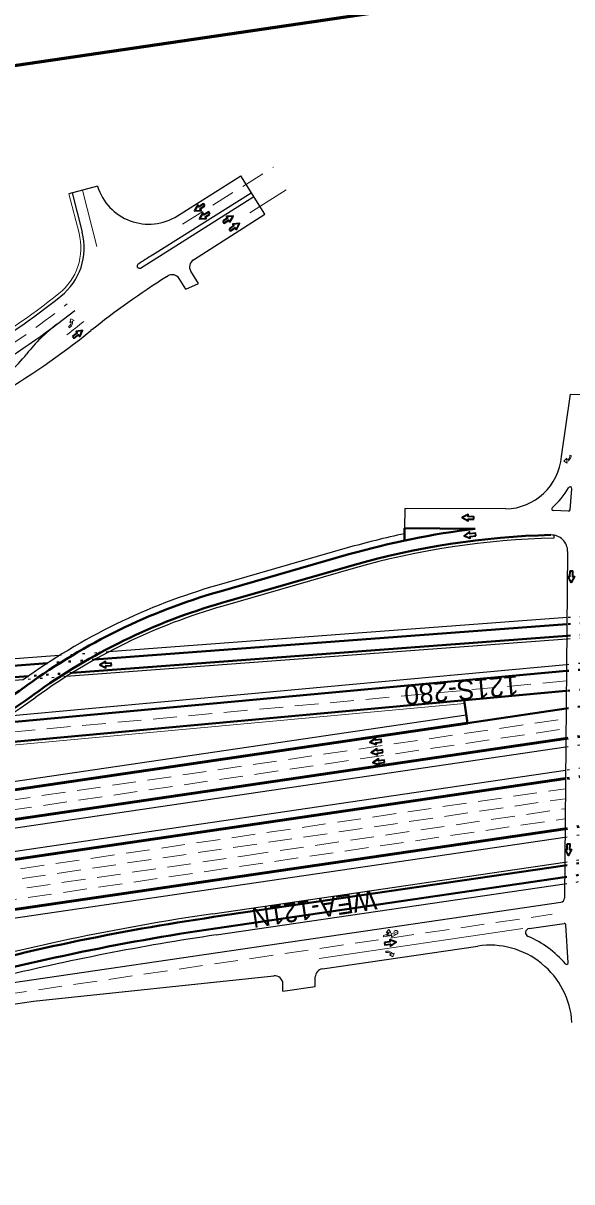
# Model space of a CAD drawing. Extents: x 2329387 to 2347382, y 6951580 to 6987999.
# Drawn here: x 2334179 to 2334845, y 6964414 to 6965820 of the extents above; entities that cross this region are included whole.
import ezdxf

# ---------------------------------------------------------------- set-up
doc = ezdxf.new("R2010")
doc.units = 0
doc.header["$LTSCALE"] = 9.6
doc.header["$PDMODE"] = 32
doc.header["$PDSIZE"] = 4.8
doc.linetypes.add('DOTTED', pattern=[1.5, 0.3, -1.2])
doc.linetypes.add('MEDIUM_DASHED', pattern=[4.5, 3, -1.5])
for name, color, linetype, lineweight in [('26', 7, 'Continuous', 53), ('27', 7, 'Continuous', 40), ('28', 7, 'Continuous', 25), ('30', 7, 'Continuous', 13), ('41', 7, 'Continuous', 35), ('50', 7, 'MEDIUM_DASHED', 13), ('60', 7, 'Continuous', 25), ('62', 7, 'Continuous', 60)]:
    doc.layers.add(name, color=color, linetype=linetype, lineweight=lineweight)
doc.layers.add('40', color=7, linetype='Continuous')

msp = doc.modelspace()

# ---------------------------------------------------------------- linework, layer by layer
at = {"layer": '26', "lineweight": 25}
for p, q in [((2333856.94, 6964854.018), (2334717.176, 6964980.367)), ((2333865.078, 6964798.612), (2334838.157, 6964941.536)), ((2333460.788, 6964710.931), (2334837.888, 6964913.196)), ((2333954.558, 6964702.596), (2334837.12, 6964832.225))]:
    msp.add_line(p, q, dxfattribs=at)
at = {"layer": '26'}
for p, q in [((2333858.393, 6964844.124), (2334718.629, 6964970.474)), ((2333863.625, 6964808.506), (2334838.253, 6964951.657)), ((2333462.241, 6964701.037), (2334837.792, 6964903.075)), ((2334058.85, 6964728.022), (2334837.216, 6964842.346))]:
    msp.add_line(p, q, dxfattribs=at)
at = {"layer": '26', "linetype": 'DOTTED', "lineweight": 25}
for p, q in [((2334838.157, 6964941.536), (2334914.266, 6964952.715)), ((2334913.997, 6964924.375), (2334837.888, 6964913.196)), ((2334837.12, 6964832.225), (2334913.23, 6964843.404))]:
    msp.add_line(p, q, dxfattribs=at)
at = {"layer": '26', "linetype": 'DOTTED'}
for p, q in [((2334838.253, 6964951.657), (2334914.362, 6964962.836)), ((2334913.901, 6964914.254), (2334837.792, 6964903.075)), ((2334837.216, 6964842.346), (2334913.326, 6964853.525))]:
    msp.add_line(p, q, dxfattribs=at)
at = {"layer": '27'}
for p, q in [((2334642.281, 6965192.145), (2334642.431, 6965207.145)), ((2334642.431, 6965207.145), (2334728.038, 6965206.29)), ((2334574.816, 6965175.343), (2334416.81, 6965129.922)), ((2334578.683, 6965161.887), (2334420.678, 6965116.467)), ((2334839.569, 6965090.471), (2334265.921, 6965047.543)), ((2334839.436, 6965076.422), (2334238.653, 6965031.463)), ((2334208.79, 6965043.268), (2333525.879, 6964992.163)), ((2334185.648, 6965027.497), (2333498.596, 6964976.082)), ((2334146.832, 6964969.959), (2334839.031, 6965033.749)), ((2334838.802, 6965009.626), (2334095.849, 6964941.159)), ((2334714.561, 6964998.176), (2334718.629, 6964970.474)), ((2334718.629, 6964970.474), (2334838.598, 6964988.094)), ((2334410.301, 6964735.17), (2334836.794, 6964797.812)), ((2334412.335, 6964721.319), (2334836.659, 6964783.642))]:
    msp.add_line(p, q, dxfattribs=at)
at = {"layer": '27', "lineweight": 25}
for p, q in [((2334823.447, 6965198.918), (2334823.529, 6965194.919)), ((2334572.605, 6965183.031), (2334414.6, 6965137.611)), ((2334579.788, 6965158.043), (2334421.783, 6965112.623)), ((2334839.645, 6965098.499), (2334283.038, 6965056.846)), ((2334839.398, 6965072.408), (2334231.393, 6965026.909)), ((2334223.01, 6965052.354), (2333541.47, 6965001.352)), ((2334161.708, 6964979.364), (2334839.107, 6965041.79)), ((2334179.397, 6965023.018), (2333490.801, 6964971.488)), ((2334409.719, 6964739.127), (2334836.832, 6964801.861)), ((2334413.498, 6964713.403), (2334836.583, 6964775.545))]:
    msp.add_line(p, q, dxfattribs=at)
at = {"layer": '27', "linetype": 'DOTTED'}
for p, q in [((2334915.626, 6965096.163), (2334839.569, 6965090.471)), ((2334915.493, 6965082.113), (2334839.436, 6965076.422)), ((2334265.921, 6965047.543), (2334214.256, 6965043.677)), ((2334839.031, 6965033.749), (2334915.101, 6965040.759)), ((2334238.653, 6965031.463), (2334185.648, 6965027.497)), ((2334914.872, 6965016.636), (2334838.802, 6965009.626)), ((2334838.598, 6964988.094), (2334914.708, 6964999.273)), ((2334836.794, 6964797.812), (2334912.903, 6964808.991)), ((2334836.659, 6964783.642), (2334912.769, 6964794.821))]:
    msp.add_line(p, q, dxfattribs=at)
at = {"layer": '27', "linetype": 'DOTTED', "lineweight": 25}
for p, q in [((2334915.575, 6965104.181), (2334839.645, 6965098.499)), ((2334915.455, 6965078.099), (2334839.398, 6965072.408)), ((2334283.038, 6965056.846), (2334225.125, 6965052.513)), ((2334839.107, 6965041.79), (2334915.177, 6965048.8)), ((2334231.393, 6965026.909), (2334179.397, 6965023.018)), ((2334836.832, 6964801.861), (2334912.942, 6964813.04)), ((2334836.583, 6964775.545), (2334912.692, 6964786.724))]:
    msp.add_line(p, q, dxfattribs=at)
at = {"layer": '27', "lineweight": 13}
msp.add_line((2334715.143, 6964994.213), (2334086.159, 6964936.249), dxfattribs=at)
at = {"layer": '27'}
for centre, radius, start, end in [((2339406.145, 6959556.474), 7976, 170.51466, 170.51466), ((2334842.948, 6964242.579), 970.538, 96.79971, 106.03781), ((2334842.948, 6964242.579), 956.538, 91.37922, 106.03791), ((2334624.015, 6964409.113), 750, 106.03791, 125.92709), ((2334624.015, 6964409.113), 736, 106.03791, 125.92709), ((2333743.882, 6965623.759), 750, 278.35573, 305.92709), ((2333743.882, 6965623.759), 764, 278.35573, 305.92709), ((2334828.642, 6961886.94), 2878.789, 98.35573, 105.37884), ((2334828.642, 6961886.94), 2864.789, 98.35573, 105.37884)]:
    msp.add_arc(centre, radius, start, end, dxfattribs=at)
at = {"layer": '27', "lineweight": 25}
for centre, radius, start, end in [((2334842.948, 6964242.579), 978.538, 101.82861, 106.03781), ((2334842.948, 6964242.579), 952.538, 91.16817, 106.03791), ((2334624.015, 6964409.113), 758, 106.03791, 125.92709), ((2334624.015, 6964409.113), 732, 106.03791, 125.92709), ((2333743.882, 6965623.759), 768, 278.35573, 305.92709), ((2334828.642, 6961886.94), 2882.789, 98.35573, 105.37884), ((2334828.642, 6961886.94), 2856.789, 98.35573, 103.83151)]:
    msp.add_arc(centre, radius, start, end, dxfattribs=at)
at = {"layer": '28'}
for p, q in [((2334366.494, 6965586.06), (2334443.436, 6965634.56)), ((2334472.751, 6965588.054), (2334443.436, 6965634.56)), ((2334269.683, 6965622.011), (2334234.765, 6965612.992)), ((2334238.638, 6965613.992), (2334250.993, 6965566.156)), ((2334336.431, 6965538.74), (2334456.234, 6965614.257)), ((2334321.554, 6965522.86), (2334459.166, 6965609.604)), ((2334385.955, 6965532.721), (2334472.751, 6965588.054)), ((2334353.229, 6965512.092), (2334354.944, 6965513.173)), ((2334832.876, 6965294.023), (2334844.015, 6965369.845)), ((2334844.028, 6965369.845), (2334913.874, 6965369.183)), ((2334843.4, 6965229.553), (2334845.307, 6965255.024)), ((2334841.329, 6965227.704), (2334822.856, 6965228.408)), ((2334840.405, 6965178.656), (2334836.417, 6964758.062)), ((2334146.907, 6964652.517), (2334832.144, 6964753.163)), ((2334793.517, 6964721.21), (2334836.014, 6964727.452)), ((2334841.153, 6964679.739), (2334838.301, 6964725.598)), ((2334542.559, 6964672.221), (2334731.324, 6964699.947)), ((2334191.855, 6964632.839), (2334483.531, 6964663.831)), ((2334533.946, 6964650.742), (2334534.012, 6964662.384)), ((2334494.538, 6964644.954), (2334494.588, 6964653.831)), ((2334494.538, 6964644.954), (2334533.946, 6964650.742)), ((2333814.811, 6964577.46), (2334191.855, 6964632.839))]:
    msp.add_line(p, q, dxfattribs=at)
at = {"layer": '28', "lineweight": 13}
msp.add_line((2334538.709, 6964684.795), (2334786.13, 6964721.136), dxfattribs=at)
at = {"layer": '28'}
msp.add_lwpolyline([(2334765.219, 6965230.4), (2334642.681, 6965230.938), (2334642.431, 6965207.145)], dxfattribs=at)
for centre, radius, start, end in [((2334331.833, 6965641.047), 65, 197.02964, 302.22536), ((2334178.376, 6965547.4), 75, 308.53995, 14.48202), ((2334886.479, 6964666.135), 1031.5, 122.22536, 123.3977), ((2334886.479, 6964666.135), 1000, 122.22536, 128.67685), ((2333636.625, 6966227.501), 944.5, 300.51546, 308.53995), ((2333636.625, 6966227.501), 968.5, 300.51546, 308.67685), ((2333636.625, 6966227.501), 1000, 300.51546, 308.67685), ((2334340.839, 6965295.044), 200, 127.06101, 141.87247), ((2334053.12, 6965520.868), 165.757, 300.51546, 321.87247), ((2334763.208, 6965300.324), 69.953, 271.64718, 354.83201), ((2334763.208, 6965300.324), 89.953, 310.50417, 330.59272), ((2334843.313, 6965255.174), 2, 355.71736, 150.59272), ((2334822.932, 6965230.407), 2, 130.50417, 267.81725), ((2334841.405, 6965229.703), 2, 267.81724, 355.71735), ((2334820.406, 6965178.845), 20, 359.45667, 91.37922), ((2334831.417, 6964758.109), 5, 278.35573, 359.45667), ((2334836.305, 6964725.473), 2, 3.55868, 98.35573), ((2334794.243, 6964716.263), 5, 98.35573, 247.22612), ((2334745.856, 6964601.008), 100, 3.55868, 98.35573), ((2334745.856, 6964601.008), 120, 40.11433, 67.22612), ((2334544.012, 6964662.327), 10, 98.35573, 179.67402), ((2334839.157, 6964679.615), 2, 220.11433, 3.55868), ((2334484.588, 6964653.887), 10, 359.67996, 96.06512)]:
    msp.add_arc(centre, radius, start, end, dxfattribs=at)
at = {"layer": '30'}
for points in [[(2334237.598, 6965457.775), (2334235.786, 6965456.6), (2334237.166, 6965461.308)], [(2334237.166, 6965461.308), (2334241.266, 6965459.104), (2334239.075, 6965458.329)], [(2334236.271, 6965451.148), (2334235.065, 6965450.362), (2334234.216, 6965451.671), (2334235.282, 6965452.363)], [(2334839.191, 6965289.788), (2334839.436, 6965291.934), (2334835.836, 6965288.601)], [(2334844.533, 6965293.927), (2334844.699, 6965295.358), (2334843.149, 6965295.535), (2334843.005, 6965294.272)], [(2334835.836, 6965288.601), (2334839.634, 6965285.912), (2334839.352, 6965288.219)], [(2334632.186, 6964713.915), (2334626.572, 6964710.804), (2334626.79, 6964712.654), (2334616.912, 6964711.232), (2334616.69, 6964712.776), (2334618.105, 6964712.98)], [(2334622.354, 6964716.663), (2334620.216, 6964716.355), (2334623.281, 6964720.191), (2334625.797, 6964716.188), (2334623.624, 6964716.631)], [(2334620.952, 6964712.783), (2334626.654, 6964713.604), (2334625.922, 6964715.317), (2334632.186, 6964713.915)], [(2334620.916, 6964693.793), (2334619.492, 6964693.581), (2334619.724, 6964692.038), (2334620.981, 6964692.227)], [(2334626.303, 6964689.711), (2334624.167, 6964689.389), (2334628.322, 6964686.78)], [(2334628.322, 6964686.78), (2334629.93, 6964691.148), (2334627.776, 6964690.275)]]:
    msp.add_lwpolyline(points, dxfattribs=at)
for centre, radius, start, end in [((2334232.411, 6965456.793), 5.28, 302.96275, 10.71349), ((2334232.411, 6965456.793), 6.84, 304.36366, 12.97227), ((2334837.759, 6965294.869), 5.28, 285.73696, 353.48769), ((2334837.759, 6965294.869), 6.84, 283.47817, 352.08678), ((2334617.365, 6964718.127), 5.2, 278.19083, 343.64684), ((2334617.365, 6964718.127), 6.436, 303.88162, 346.56565), ((2334621.768, 6964687.006), 6.84, 28.55446, 97.16307), ((2334621.768, 6964687.006), 5.28, 30.81324, 98.56398)]:
    msp.add_arc(centre, radius, start, end, dxfattribs=at)
msp.add_point((2334631.815, 6964716.489), dxfattribs=at)
at = {"layer": '41'}
for points in [[(2334399.929, 6965598.18), (2334398.35, 6965600.732), (2334392.562, 6965597.151), (2334391.279, 6965599.224), (2334387.144, 6965592.222), (2334395.256, 6965592.797), (2334394.141, 6965594.599)], [(2334406.118, 6965588.338), (2334404.539, 6965590.89), (2334398.751, 6965587.309), (2334397.468, 6965589.381), (2334393.333, 6965582.38), (2334401.444, 6965582.954), (2334400.329, 6965584.757)], [(2334421.662, 6965579.708), (2334423.292, 6965577.189), (2334429.006, 6965580.888), (2334430.331, 6965578.842), (2334434.321, 6965585.927), (2334426.224, 6965585.187), (2334427.375, 6965583.407)], [(2334429.435, 6965570.576), (2334431.065, 6965568.057), (2334436.779, 6965571.756), (2334438.104, 6965569.71), (2334442.094, 6965576.795), (2334433.997, 6965576.054), (2334435.148, 6965574.275)], [(2334239.282, 6965440.058), (2334241.088, 6965437.662), (2334246.524, 6965441.759), (2334247.991, 6965439.812), (2334251.466, 6965447.164), (2334243.442, 6965445.848), (2334244.718, 6965444.155)], [(2334726.315, 6965217.985), (2334726.363, 6965220.986), (2334719.557, 6965221.094), (2334719.596, 6965223.531), (2334712.336, 6965219.868), (2334719.475, 6965215.975), (2334719.509, 6965218.094)], [(2334728.718, 6965197.91), (2334728.354, 6965200.889), (2334721.597, 6965200.063), (2334721.302, 6965202.482), (2334714.613, 6965197.857), (2334722.219, 6965194.98), (2334721.962, 6965197.084)], [(2334843.258, 6965155.282), (2334846.259, 6965155.236), (2334846.155, 6965148.43), (2334848.592, 6965148.393), (2334844.703, 6965141.252), (2334841.035, 6965148.509), (2334843.154, 6965148.476)], [(2334286.361, 6965040.396), (2334286.142, 6965043.389), (2334279.353, 6965042.893), (2334279.176, 6965045.323), (2334272.27, 6965041.03), (2334279.726, 6965037.786), (2334279.572, 6965039.9)], [(2334614.369, 6964947.507), (2334613.98, 6964950.483), (2334607.231, 6964949.602), (2334606.916, 6964952.019), (2334600.265, 6964947.34), (2334607.893, 6964944.525), (2334607.619, 6964946.626)], [(2334616.086, 6964934.938), (2334615.698, 6964937.913), (2334608.948, 6964937.033), (2334608.633, 6964939.45), (2334601.982, 6964934.771), (2334609.611, 6964931.956), (2334609.336, 6964934.057)], [(2334618.002, 6964922.693), (2334617.614, 6964925.669), (2334610.864, 6964924.788), (2334610.549, 6964927.205), (2334603.898, 6964922.526), (2334611.526, 6964919.711), (2334611.252, 6964921.813)], [(2334839.88, 6964823.902), (2334842.881, 6964823.874), (2334842.816, 6964817.067), (2334845.253, 6964817.044), (2334841.406, 6964809.88), (2334837.696, 6964817.116), (2334839.815, 6964817.096)], [(2334617.938, 6964704.259), (2334618.365, 6964701.288), (2334625.103, 6964702.258), (2334625.45, 6964699.846), (2334632.038, 6964704.612), (2334624.373, 6964707.326), (2334624.675, 6964705.229)]]:
    msp.add_lwpolyline(points, close=True, dxfattribs=at)
at = {"layer": '50'}
for p, q in [((2334372.893, 6965575.908), (2334483.089, 6965645.371)), ((2334838.917, 6965021.687), (2334122.695, 6964955.684)), ((2333860.137, 6964832.251), (2334838.483, 6964975.949)), ((2333861.881, 6964820.379), (2334838.368, 6964963.803)), ((2332979.358, 6964617.983), (2334837.677, 6964890.929)), ((2332981.102, 6964606.111), (2334837.562, 6964878.783)), ((2334057.106, 6964739.894), (2334837.331, 6964854.492)), ((2334448.416, 6964809.498), (2334837.446, 6964866.638)), ((2334055.362, 6964751.767), (2334448.416, 6964809.498)), ((2333813.025, 6964590.337), (2334821.609, 6964738.476))]:
    msp.add_line(p, q, dxfattribs=at)
at = {"layer": '50', "linetype": 'Continuous'}
for p, q in [((2334234.765, 6965612.992), (2334247.12, 6965565.157)), ((2334251.225, 6965617.243), (2334268.887, 6965548.859)), ((2334454.305, 6965589.99), (2334498.516, 6965617.859))]:
    msp.add_line(p, q, dxfattribs=at)
for centre, radius, start, end in [((2334178.376, 6965547.4), 71, 308.53995, 14.48315), ((2333636.625, 6966227.501), 940.5, 300.51546, 308.53995), ((2333636.625, 6966227.501), 986, 307.17968, 308.67685)]:
    msp.add_arc(centre, radius, start, end, dxfattribs=at)
at = {"layer": '50'}
msp.add_arc((2333636.625, 6966227.501), 956.5, 300.51546, 308.53995, dxfattribs=at)
at = {"layer": '60'}
for p, q in [((2334318.106, 6965523.642), (2334317.954, 6965523.883)), ((2334392.205, 6965504.052), (2334382.828, 6965518.929)), ((2334376.787, 6965497.275), (2334368.736, 6965510.046)), ((2334376.787, 6965497.275), (2334392.205, 6965504.052))]:
    msp.add_line(p, q, dxfattribs=at)
for centre, radius, start, end in [((2334391.287, 6965524.261), 10, 122.22535, 212.22535), ((2334320.069, 6965525.216), 2.5, 123.3977, 212.22536), ((2334320.221, 6965524.975), 2.5, 212.22535, 302.22535), ((2334360.277, 6965504.714), 10, 32.22535, 122.22535)]:
    msp.add_arc(centre, radius, start, end, dxfattribs=at)
at = {"layer": '62'}
msp.add_lwpolyline([(2338114.665, 6964428.225), (2329704.893, 6963193.017), (2329428.787, 6965072.851), (2337838.559, 6966308.058)], close=True, dxfattribs=at)

# ---------------------------------------------------------------- texts
at = {"layer": '40'}
msp.add_text('121S-280', height=24, rotation=185.089, dxfattribs=at).set_placement((2334779.603, 6965028.628))
at = {"layer": '40', "width": 0.95}
msp.add_text('WEA-121N', height=24, rotation=188.63, dxfattribs=at).set_placement((2334606.257, 6964768.405))

doc.saveas('drawing.dxf')
